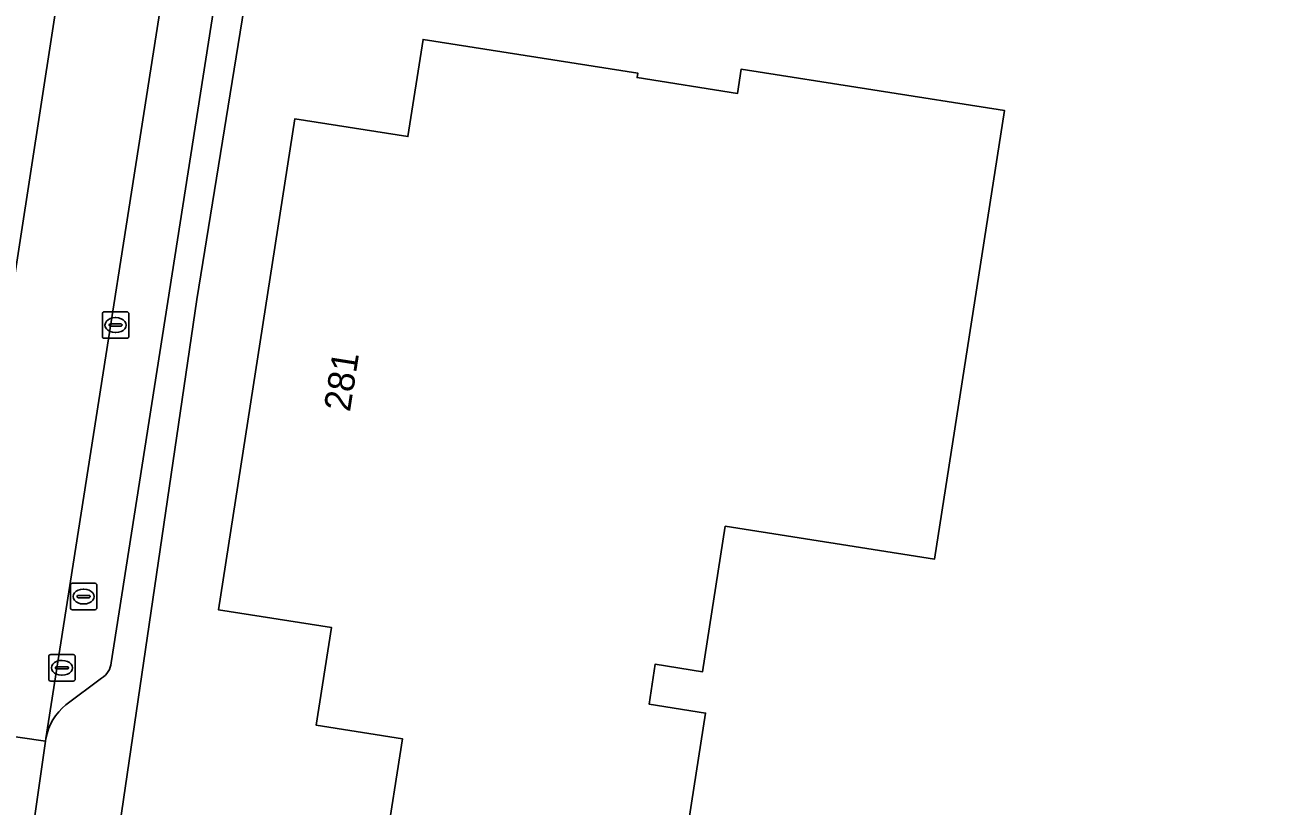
# Model space of a CAD drawing. Extents: x 161483 to 162250, y 379484 to 380833.
# Drawn here: x 161646.16 to 161693.19, y 380408.38 to 380437.87 of the extents above; entities that cross this region are included whole.
import ezdxf

# ---------------------------------------------------------------- set-up
doc = ezdxf.new("R2010")
doc.units = 0
for name, color, linetype in [('IMGEO_Berm_groen', 7, 'Continuous'), ('IMGEO_Brandkraan', 7, 'Continuous'), ('IMGEO_Erf', 7, 'Continuous'), ('IMGEO_Kolk', 7, 'Continuous'), ('IMGEO_Pand', 7, 'Continuous'), ('IMGEO_Pand_nummerreeks', 7, 'Continuous'), ('IMGEO_Parkeervlak_open', 7, 'Continuous'), ('IMGEO_Rijbaan_lokaal_open', 7, 'Continuous'), ('IMGEO_Voetpad_open', 7, 'Continuous')]:
    doc.layers.add(name, color=color, linetype=linetype)

msp = doc.modelspace()

# ---------------------------------------------------------------- linework, layer by layer
at = {"layer": 'IMGEO_Berm_groen'}
msp.add_lwpolyline([(161641.836, 380407.962), (161642.249, 380408.063), (161642.538, 380408.239), (161642.658, 380408.596), (161643.106, 380411.379), (161643.632, 380414.648), (161645.563, 380427.034), (161647.987, 380442.726), (161648.528, 380446.179)], dxfattribs=at)
at = {"layer": 'IMGEO_Brandkraan'}
for p, q in [((161647.955, 380416.789), (161648.807, 380416.789)), ((161647.88, 380415.863), (161647.88, 380416.715)), ((161648.139, 380416.283), (161648.139, 380416.295)), ((161648.182, 380416.332), (161648.58, 380416.332)), ((161648.368, 380416.569), (161648.393, 380416.569)), ((161648.623, 380416.295), (161648.623, 380416.283)), ((161648.881, 380416.715), (161648.881, 380415.863)), ((161648.577, 380416.246), (161648.179, 380416.246)), ((161648.391, 380416.009), (161648.366, 380416.009)), ((161648.807, 380415.789), (161647.955, 380415.789))]:
    msp.add_line(p, q, dxfattribs=at)
for points in [[(161647.955, 380416.789), (161648.807, 380416.789)], [(161647.88, 380415.863), (161647.88, 380416.715)], [(161648.881, 380416.715), (161648.881, 380415.863)], [(161648.807, 380415.789), (161647.955, 380415.789)]]:
    msp.add_lwpolyline(points, dxfattribs=at)
for centre, radius, start, end in [((161647.957, 380416.713), 0.0765, 91.552, 178.448), ((161647.957, 380416.713), 0.0765, 91.552, 178.448), ((161648.805, 380416.713), 0.0765, 1.552, 88.448), ((161648.805, 380416.713), 0.0765, 1.552, 88.448), ((161648.179, 380416.292), 0.0403, 85.8775, 175.7526), ((161648.176, 380416.282), 0.0366, 178.938, 274.7102), ((161648.58, 380416.289), 0.043, 264.8664, 352.4533), ((161648.584, 380416.294), 0.0386, 1.7309, 96.639), ((161647.957, 380415.865), 0.0765, 181.552, 268.448), ((161647.957, 380415.865), 0.0765, 181.552, 268.448), ((161648.805, 380415.865), 0.0765, 271.552, 358.448), ((161648.805, 380415.865), 0.0765, 271.552, 358.448)]:
    msp.add_arc(centre, radius, start, end, dxfattribs=at)
for centre, major_axis, ratio, start_param, end_param in [((161648.367, 380416.289), (-0.387, 0.002), 0.722429, 4.712389, 7.853982), ((161648.392, 380416.289), (-0.39, 0.002), 0.717154, 1.570796, 4.712389)]:
    msp.add_ellipse(centre, major_axis=major_axis, ratio=ratio, start_param=start_param, end_param=end_param, dxfattribs=at)
at = {"layer": 'IMGEO_Erf'}
msp.add_lwpolyline([(161655.481, 380444.917), (161652.656, 380427.511), (161649.605, 380406.735), (161650.001, 380406.676), (161673.199, 380388.404), (161682.464, 380380.888), (161735.153, 380373.873), (161748.237, 380371.945), (161806.448, 380361.939)], dxfattribs=at)
msp.add_lwpolyline([(161659.762, 380406.657), (161660.426, 380410.915), (161657.166, 380411.427), (161657.742, 380415.123), (161653.474, 380415.793), (161656.362, 380434.33), (161660.63, 380433.66), (161661.201, 380437.326), (161669.312, 380436.052), (161669.286, 380435.884), (161673.079, 380435.288), (161673.222, 380436.207), (161683.16, 380434.647), (161680.52, 380417.701), (161672.617, 380418.942), (161671.761, 380413.448), (161669.967, 380413.73), (161669.736, 380412.227), (161671.873, 380411.891), (161670.787, 380404.925)], close=True, dxfattribs=at)
at = {"layer": 'IMGEO_Kolk'}
for p, q in [((161649.087, 380426.114), (161649.087, 380426.966)), ((161649.162, 380427.04), (161650.014, 380427.04)), ((161649.575, 380426.82), (161649.6, 380426.82)), ((161650.088, 380426.966), (161650.088, 380426.114)), ((161649.346, 380426.534), (161649.346, 380426.546)), ((161649.784, 380426.497), (161649.386, 380426.497)), ((161649.389, 380426.583), (161649.787, 380426.583)), ((161649.598, 380426.26), (161649.573, 380426.26)), ((161649.83, 380426.546), (161649.83, 380426.534)), ((161650.014, 380426.04), (161649.162, 380426.04)), ((161647.061, 380413.172), (161647.061, 380414.024)), ((161647.136, 380414.098), (161647.988, 380414.098)), ((161648.062, 380414.024), (161648.062, 380413.172)), ((161647.32, 380413.592), (161647.32, 380413.604)), ((161647.758, 380413.555), (161647.36, 380413.555)), ((161647.363, 380413.641), (161647.761, 380413.641)), ((161647.549, 380413.878), (161647.574, 380413.878)), ((161647.804, 380413.604), (161647.804, 380413.592)), ((161647.988, 380413.098), (161647.136, 380413.098)), ((161647.572, 380413.318), (161647.547, 380413.318))]:
    msp.add_line(p, q, dxfattribs=at)
for points in [[(161649.087, 380426.114), (161649.087, 380426.966)], [(161649.162, 380427.04), (161650.014, 380427.04)], [(161650.088, 380426.966), (161650.088, 380426.114)], [(161650.014, 380426.04), (161649.162, 380426.04)], [(161647.061, 380413.172), (161647.061, 380414.024)], [(161647.136, 380414.098), (161647.988, 380414.098)], [(161648.062, 380414.024), (161648.062, 380413.172)], [(161647.988, 380413.098), (161647.136, 380413.098)]]:
    msp.add_lwpolyline(points, dxfattribs=at)
for centre, radius, start, end in [((161649.164, 380426.964), 0.0765, 91.552, 178.448), ((161649.164, 380426.964), 0.0765, 91.552, 178.448), ((161650.012, 380426.964), 0.0765, 1.552, 88.448), ((161650.012, 380426.964), 0.0765, 1.552, 88.448), ((161649.386, 380426.543), 0.0403, 85.8775, 175.7526), ((161649.383, 380426.533), 0.0366, 178.938, 274.7102), ((161649.787, 380426.54), 0.043, 264.8664, 352.4533), ((161649.791, 380426.545), 0.0386, 1.7309, 96.639), ((161649.164, 380426.116), 0.0765, 181.552, 268.448), ((161649.164, 380426.116), 0.0765, 181.552, 268.448), ((161650.012, 380426.116), 0.0765, 271.552, 358.448), ((161650.012, 380426.116), 0.0765, 271.552, 358.448), ((161647.138, 380414.022), 0.0765, 91.552, 178.448), ((161647.138, 380414.022), 0.0765, 91.552, 178.448), ((161647.986, 380414.022), 0.0765, 1.552, 88.448), ((161647.986, 380414.022), 0.0765, 1.552, 88.448), ((161647.36, 380413.601), 0.0403, 85.8775, 175.7526), ((161647.357, 380413.591), 0.0366, 178.938, 274.7102), ((161647.761, 380413.598), 0.043, 264.8664, 352.4533), ((161647.765, 380413.603), 0.0386, 1.7309, 96.639), ((161647.138, 380413.174), 0.0765, 181.552, 268.448), ((161647.138, 380413.174), 0.0765, 181.552, 268.448), ((161647.986, 380413.174), 0.0765, 271.552, 358.448), ((161647.986, 380413.174), 0.0765, 271.552, 358.448)]:
    msp.add_arc(centre, radius, start, end, dxfattribs=at)
for centre, major_axis, ratio, start_param, end_param in [((161649.574, 380426.54), (-0.387, 0.002), 0.722429, 4.712389, 7.853982), ((161649.599, 380426.54), (-0.39, 0.002), 0.717154, 1.570796, 4.712389), ((161647.548, 380413.598), (-0.387, 0.002), 0.722429, 4.712389, 7.853982), ((161647.573, 380413.598), (-0.39, 0.002), 0.717154, 1.570796, 4.712389)]:
    msp.add_ellipse(centre, major_axis=major_axis, ratio=ratio, start_param=start_param, end_param=end_param, dxfattribs=at)
at = {"layer": 'IMGEO_Pand'}
msp.add_lwpolyline([(161670.787, 380404.925), (161671.873, 380411.891), (161669.736, 380412.227), (161669.967, 380413.73), (161671.761, 380413.448), (161672.617, 380418.942), (161680.52, 380417.701), (161683.16, 380434.647), (161673.222, 380436.207), (161673.079, 380435.288), (161669.286, 380435.884), (161669.312, 380436.052), (161661.201, 380437.326), (161660.63, 380433.66), (161656.362, 380434.33), (161653.474, 380415.793), (161657.742, 380415.123), (161657.166, 380411.427), (161660.426, 380410.915), (161659.762, 380406.657)], close=True, dxfattribs=at)
at = {"layer": 'IMGEO_Parkeervlak_open'}
for points in [[(161652.348, 380445.377), (161646.956, 380410.929)], [(161649.421, 380413.792), (161653.859, 380442.125)], [(161647.711, 380412.198), (161649.061, 380413.207)]]:
    msp.add_lwpolyline(points, dxfattribs=at)
for centre, radius, start, end in [((161648.658, 380413.858), 0.766, 301.7462, 355.0388), ((161649.035, 380410.551), 2.113, 128.7963, 169.7021)]:
    msp.add_arc(centre, radius, start, end, dxfattribs=at)
at = {"layer": 'IMGEO_Rijbaan_lokaal_open'}
for points in [[(161652.348, 380445.377), (161652.379, 380445.573), (161648.528, 380446.179), (161647.987, 380442.726), (161645.563, 380427.034), (161643.632, 380414.648), (161643.106, 380411.379), (161646.94, 380410.827), (161646.956, 380410.929)], [(161646.94, 380410.827), (161643.106, 380411.379), (161642.658, 380408.596), (161642.538, 380408.239), (161646.482, 380407.658)]]:
    msp.add_lwpolyline(points, close=True, dxfattribs=at)
at = {"layer": 'IMGEO_Voetpad_open'}
for points in [[(161647.801, 380395.571), (161649.233, 380404.254), (161649.605, 380406.735), (161652.656, 380427.511), (161655.481, 380444.917)], [(161653.859, 380442.125), (161649.421, 380413.792)], [(161649.061, 380413.207), (161647.711, 380412.198)], [(161646.956, 380410.929), (161646.94, 380410.827), (161646.482, 380407.658)]]:
    msp.add_lwpolyline(points, dxfattribs=at)
for centre, radius, start, end in [((161648.658, 380413.858), 0.766, 301.7462, 355.0388), ((161649.035, 380410.551), 2.113, 128.7963, 169.7021)]:
    msp.add_arc(centre, radius, start, end, dxfattribs=at)

# ---------------------------------------------------------------- texts
at = {"layer": 'IMGEO_Pand_nummerreeks'}
msp.add_text('281', height=1, rotation=81.0704, dxfattribs=at).set_placement((161658.437, 380423.236))

doc.saveas('drawing.dxf')
